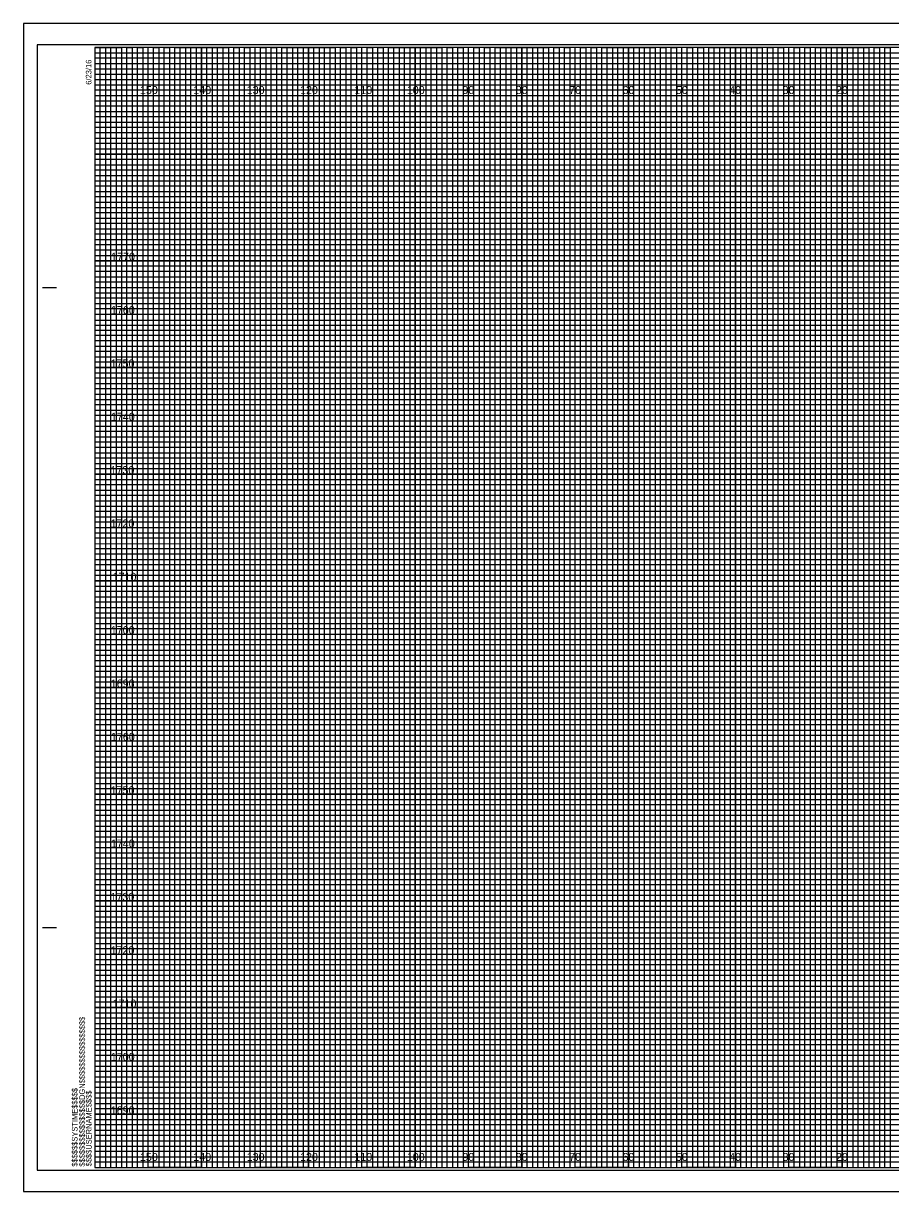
# Model space of a CAD drawing. Extents: x -13 to 1780, y -15 to 3284.
# Drawn here: x 1443.3 to 1605.8, y 865.2 to 1084.2 of the extents above; entities that cross this region are included whole.
import ezdxf

# ---------------------------------------------------------------- set-up
doc = ezdxf.new("R2010")
doc.units = 0
for name, color, linetype in [('Prop Retaining Wall', 7, 'Continuous'), ('Prop SS Cut Line', 7, 'Continuous'), ('Prop SS Fill Line', 7, 'Continuous'), ('Prop SS Transition Line', 7, 'Continuous'), ('Prop XS Earthwork Shape', 7, 'Continuous'), ('Prop XS Noise Wall', 7, 'Continuous'), ('Prop XS Station Labels', 7, 'Continuous'), ('Raster_Level_0', 7, 'Continuous'), ('Scratch_Level_3', 7, 'Continuous'), ('Scratch_Level_7', 7, 'Continuous'), ('Typical Bridge Rail CELL', 7, 'Continuous')]:
    doc.layers.add(name, color=color, linetype=linetype)

msp = doc.modelspace()

# ---------------------------------------------------------------- linework, layer by layer
at = {"layer": 'Prop Retaining Wall'}
for p, q in [((1446.88, 1034.71), (1449.38, 1034.71)), ((1446.98, 1034.71), (1449.48, 1034.71)), ((1446.88, 914.71), (1449.38, 914.71)), ((1446.98, 914.71), (1449.48, 914.71)), ((1456.68, 869.71), (1456.68, 869.71)), ((1456.68, 869.71), (1456.68, 869.71)), ((1456.68, 869.71), (1456.68, 869.71)), ((1456.68, 869.71), (1456.68, 869.71)), ((1456.68, 869.71), (1456.68, 869.71)), ((1456.68, 869.71), (1456.68, 869.71)), ((1456.68, 869.71), (1456.68, 869.71))]:
    msp.add_line(p, q, dxfattribs=at)
msp.add_lwpolyline([(1776.68, 1079.71), (1456.68, 1079.71), (1456.68, 869.71), (1776.68, 869.71)], close=True, dxfattribs=at)
at = {"layer": 'Prop SS Cut Line'}
for points in [[(1456.68, 1079.71), (1461.68, 1079.71), (1461.68, 869.71), (1471.68, 869.71), (1471.68, 1079.71), (1481.68, 1079.71), (1481.68, 869.71), (1491.68, 869.71), (1491.68, 1079.71), (1501.68, 1079.71), (1501.68, 869.71), (1511.68, 869.71), (1511.68, 1079.71), (1521.68, 1079.71), (1521.68, 869.71), (1531.68, 869.71), (1531.68, 1079.71), (1541.68, 1079.71), (1541.68, 869.71), (1551.68, 869.71), (1551.68, 1079.71), (1561.68, 1079.71), (1561.68, 869.71), (1571.68, 869.71), (1571.68, 1079.71), (1581.68, 1079.71), (1581.68, 869.71), (1591.68, 869.71), (1591.68, 1079.71), (1601.68, 1079.71), (1601.68, 869.71), (1611.68, 869.71)], [(1456.68, 1074.71), (1731.68, 1074.71)], [(1456.68, 1054.71), (1776.68, 1054.71), (1776.68, 1064.71), (1456.68, 1064.71)], [(1456.68, 1034.71), (1776.68, 1034.71), (1776.68, 1044.71), (1456.68, 1044.71)], [(1456.68, 1014.71), (1776.68, 1014.71), (1776.68, 1024.71), (1456.68, 1024.71)], [(1456.68, 994.71), (1776.68, 994.71), (1776.68, 1004.71), (1456.68, 1004.71)], [(1456.68, 974.71), (1776.68, 974.71), (1776.68, 984.71), (1456.68, 984.71)], [(1456.68, 954.71), (1776.68, 954.71), (1776.68, 964.71), (1456.68, 964.71)], [(1456.68, 934.71), (1776.68, 934.71), (1776.68, 944.71), (1456.68, 944.71)], [(1456.68, 914.71), (1776.68, 914.71), (1776.68, 924.71), (1456.68, 924.71)], [(1456.68, 894.71), (1776.68, 894.71), (1776.68, 904.71), (1456.68, 904.71)], [(1456.68, 874.71), (1776.68, 874.71), (1776.68, 884.71), (1456.68, 884.71)]]:
    msp.add_lwpolyline(points, dxfattribs=at)
at = {"layer": 'Prop SS Fill Line'}
for p, q in [((1466.68, 1079.71), (1456.68, 1079.71)), ((1466.68, 869.71), (1466.68, 1079.71)), ((1486.68, 1079.71), (1476.68, 1079.71)), ((1476.68, 1079.71), (1476.68, 869.71)), ((1486.68, 869.71), (1486.68, 1079.71)), ((1506.68, 1079.71), (1496.68, 1079.71)), ((1496.68, 1079.71), (1496.68, 869.71)), ((1506.68, 869.71), (1506.68, 1079.71)), ((1526.68, 1079.71), (1516.68, 1079.71)), ((1516.68, 1079.71), (1516.68, 869.71)), ((1526.68, 869.71), (1526.68, 1079.71)), ((1546.68, 1079.71), (1536.68, 1079.71)), ((1536.68, 1079.71), (1536.68, 869.71)), ((1546.68, 869.71), (1546.68, 1079.71)), ((1566.68, 1079.71), (1556.68, 1079.71)), ((1556.68, 1079.71), (1556.68, 869.71)), ((1566.68, 869.71), (1566.68, 1079.71)), ((1586.68, 1079.71), (1576.68, 1079.71)), ((1576.68, 1079.71), (1576.68, 869.71)), ((1586.68, 869.71), (1586.68, 1079.71)), ((1606.68, 1079.71), (1596.68, 1079.71)), ((1596.68, 1079.71), (1596.68, 869.71)), ((1476.68, 869.71), (1466.68, 869.71)), ((1496.68, 869.71), (1486.68, 869.71)), ((1516.68, 869.71), (1506.68, 869.71)), ((1536.68, 869.71), (1526.68, 869.71)), ((1556.68, 869.71), (1546.68, 869.71)), ((1576.68, 869.71), (1566.68, 869.71)), ((1596.68, 869.71), (1586.68, 869.71))]:
    msp.add_line(p, q, dxfattribs=at)
for points in [[(1456.68, 1069.71), (1776.68, 1069.71), (1776.68, 1059.71), (1456.68, 1059.71)], [(1456.68, 1049.71), (1776.68, 1049.71), (1776.68, 1039.71), (1456.68, 1039.71)], [(1456.68, 1029.71), (1776.68, 1029.71), (1776.68, 1019.71), (1456.68, 1019.71)], [(1456.68, 1009.71), (1776.68, 1009.71), (1776.68, 999.71), (1456.68, 999.71)], [(1456.68, 989.71), (1776.68, 989.71), (1776.68, 979.71), (1456.68, 979.71)], [(1456.68, 969.71), (1776.68, 969.71), (1776.68, 959.71), (1456.68, 959.71)], [(1456.68, 949.71), (1776.68, 949.71), (1776.68, 939.71), (1456.68, 939.71)], [(1456.68, 929.71), (1776.68, 929.71), (1776.68, 919.71), (1456.68, 919.71)], [(1456.68, 909.71), (1776.68, 909.71), (1776.68, 899.71), (1456.68, 899.71)], [(1456.68, 889.71), (1776.68, 889.71), (1776.68, 879.71), (1456.68, 879.71)]]:
    msp.add_lwpolyline(points, dxfattribs=at)
at = {"layer": 'Prop SS Transition Line'}
for p, q in [((1456.68, 1078.71), (1716.68, 1078.71)), ((1716.68, 1077.69), (1456.68, 1077.69)), ((1456.68, 1077.69), (1456.68, 1076.71)), ((1456.68, 1076.71), (1716.68, 1076.71)), ((1716.68, 1075.6), (1456.68, 1075.6)), ((1456.68, 1075.6), (1456.68, 1073.71)), ((1456.68, 1073.71), (1776.68, 1073.71))]:
    msp.add_line(p, q, dxfattribs=at)
for points in [[(1456.68, 1072.71), (1726.68, 1072.71), (1776.68, 1072.71), (1776.68, 1071.71), (1456.68, 1071.71)], [(1456.68, 1070.71), (1776.68, 1070.71), (1776.68, 1068.71), (1456.68, 1068.71)], [(1456.68, 1067.71), (1776.68, 1067.71), (1776.68, 1066.71), (1456.68, 1066.69)], [(1456.68, 1065.71), (1776.68, 1065.71), (1776.68, 1063.71), (1456.68, 1063.71)], [(1456.68, 1062.71), (1776.68, 1062.71), (1776.68, 1061.71), (1456.68, 1061.71)], [(1456.68, 1060.71), (1776.68, 1060.71), (1776.68, 1058.71), (1456.68, 1058.71)], [(1456.68, 1057.71), (1776.68, 1057.71), (1776.68, 1056.71), (1456.68, 1056.71)], [(1456.68, 1055.71), (1776.68, 1055.71), (1776.68, 1053.71), (1456.68, 1053.71)], [(1456.68, 1052.71), (1776.68, 1052.71), (1776.68, 1051.71), (1456.68, 1051.71)], [(1456.68, 1050.71), (1776.68, 1050.71), (1776.68, 1048.71), (1456.68, 1048.71)], [(1456.68, 1047.71), (1776.68, 1047.71), (1776.68, 1046.71), (1456.68, 1046.71)], [(1456.68, 1045.71), (1776.68, 1045.71), (1776.68, 1043.66), (1776.68, 1042.71), (1776.68, 1041.71), (1456.68, 1041.71)], [(1456.68, 1043.71), (1776.68, 1043.71), (1776.68, 1042.71), (1456.68, 1042.71)], [(1456.68, 1040.71), (1776.68, 1040.71), (1776.68, 1038.71), (1456.68, 1038.74)], [(1456.68, 1038.74), (1776.68, 1038.71), (1776.68, 1037.71), (1456.68, 1037.71)], [(1456.68, 1036.71), (1776.68, 1036.71), (1776.68, 1035.71), (1456.68, 1035.71)], [(1456.68, 1033.71), (1776.68, 1033.71), (1776.68, 1032.71), (1456.68, 1032.71)], [(1456.68, 1031.71), (1776.68, 1031.71), (1776.68, 1030.71), (1456.68, 1030.71)], [(1456.61, 1028.6), (1776.68, 1028.6), (1776.68, 1027.59), (1456.61, 1027.59)], [(1456.68, 1026.71), (1776.68, 1026.71), (1776.68, 1025.71), (1456.68, 1025.71)], [(1456.68, 1023.71), (1776.68, 1023.71), (1776.68, 1022.71), (1456.68, 1022.71)], [(1456.68, 1021.71), (1776.68, 1021.71), (1776.68, 1020.71), (1456.68, 1020.71)], [(1456.68, 1018.71), (1776.68, 1018.71), (1776.68, 1017.71), (1456.68, 1017.71)], [(1456.68, 1016.71), (1776.68, 1016.71), (1776.68, 1015.71), (1456.68, 1015.71)], [(1456.68, 1013.71), (1776.68, 1013.71), (1776.68, 1012.71), (1456.68, 1012.71)], [(1456.68, 1011.71), (1776.68, 1011.71), (1776.68, 1010.71), (1456.68, 1010.71)], [(1456.68, 1008.71), (1776.68, 1008.71), (1776.67, 1007.69), (1456.68, 1007.71)], [(1456.68, 1006.71), (1776.68, 1006.71), (1776.68, 1005.71), (1456.68, 1005.71)], [(1456.68, 1003.71), (1776.68, 1003.71), (1776.68, 1002.71), (1456.68, 1002.71)], [(1456.68, 1001.71), (1776.68, 1001.71), (1776.68, 1000.71), (1456.68, 1000.71)], [(1456.68, 998.71), (1776.68, 998.71), (1776.68, 997.71), (1456.68, 997.71)], [(1456.68, 996.71), (1776.68, 996.71), (1776.68, 995.71), (1456.68, 995.71)], [(1456.68, 993.71), (1776.68, 993.71), (1776.68, 992.71), (1456.68, 992.71)], [(1456.68, 991.71), (1776.68, 991.71), (1776.68, 990.71), (1456.68, 990.71)], [(1456.68, 988.71), (1776.68, 988.71), (1776.68, 987.71), (1456.68, 987.71)], [(1456.68, 986.7), (1776.75, 986.62), (1776.68, 985.71), (1456.68, 985.71)], [(1456.68, 983.71), (1776.68, 983.71), (1776.68, 982.71), (1456.68, 982.71)], [(1456.68, 981.71), (1776.68, 981.71), (1776.68, 980.71), (1456.68, 980.71)], [(1456.68, 978.71), (1776.68, 978.71), (1776.68, 977.71), (1456.68, 977.71)], [(1456.68, 976.71), (1776.68, 976.71), (1776.68, 975.71), (1456.68, 975.71)], [(1456.68, 973.71), (1776.68, 973.71), (1776.68, 972.71), (1456.68, 972.71)], [(1456.68, 971.71), (1776.68, 971.71), (1776.68, 970.71), (1456.68, 970.71)], [(1456.68, 968.71), (1776.68, 968.71), (1776.68, 967.71), (1456.68, 967.71)], [(1456.68, 966.71), (1776.68, 966.71), (1776.68, 965.71), (1456.68, 965.71)], [(1456.68, 963.71), (1776.68, 963.71), (1776.68, 962.71), (1456.68, 962.71)], [(1456.68, 961.71), (1776.68, 961.71), (1776.68, 960.71), (1456.68, 960.71)], [(1456.68, 958.71), (1776.68, 958.71), (1776.68, 957.71), (1456.68, 957.71)], [(1456.68, 956.71), (1776.68, 956.71), (1776.68, 955.71), (1456.68, 955.71)], [(1456.68, 953.71), (1776.68, 953.71), (1776.68, 952.71), (1456.68, 952.71)], [(1456.68, 951.71), (1776.68, 951.71), (1776.68, 950.71), (1456.68, 950.71)], [(1456.68, 948.71), (1776.68, 948.71), (1776.67, 947.69), (1456.68, 947.71)], [(1456.68, 946.71), (1776.68, 946.71), (1776.68, 945.71), (1456.68, 945.71)], [(1456.68, 943.71), (1776.68, 943.71), (1776.68, 942.71), (1456.68, 942.71)], [(1456.68, 941.71), (1776.68, 941.71), (1776.68, 940.71), (1456.68, 940.71)], [(1456.68, 938.71), (1776.68, 938.71), (1776.68, 937.71), (1456.68, 937.71)], [(1456.68, 936.71), (1776.68, 936.71), (1776.68, 935.71), (1456.68, 935.71)], [(1456.68, 933.71), (1776.68, 933.71), (1776.68, 932.71), (1456.68, 932.71)], [(1456.68, 931.71), (1776.68, 931.71), (1776.68, 930.71), (1456.68, 930.71)], [(1456.68, 928.71), (1776.68, 928.71), (1776.68, 927.71), (1456.68, 927.71)], [(1456.68, 926.7), (1776.75, 926.62), (1776.68, 925.71), (1456.68, 925.71)], [(1456.68, 923.71), (1776.68, 923.71), (1776.68, 922.71), (1456.68, 922.71)], [(1456.68, 921.71), (1776.68, 921.71), (1776.68, 920.71), (1456.68, 920.71)], [(1456.68, 918.71), (1776.68, 918.71), (1776.68, 917.71), (1456.68, 917.71)], [(1456.68, 916.71), (1776.68, 916.71), (1776.68, 915.71), (1456.68, 915.71)], [(1456.68, 913.71), (1776.68, 913.71), (1776.68, 912.71), (1456.68, 912.71)], [(1456.68, 911.71), (1776.68, 911.71), (1776.68, 910.71), (1456.68, 910.71)], [(1456.68, 908.71), (1776.68, 908.71), (1776.68, 907.71), (1456.68, 907.71)], [(1456.68, 906.71), (1776.68, 906.71), (1776.68, 905.71), (1456.68, 905.71)], [(1456.68, 903.71), (1776.68, 903.71), (1776.68, 902.71), (1456.68, 902.71)], [(1456.68, 901.71), (1776.68, 901.71), (1776.68, 900.71), (1456.68, 900.71)], [(1456.68, 898.71), (1776.68, 898.71), (1776.68, 897.71), (1456.68, 897.71)], [(1456.68, 896.71), (1776.68, 896.71), (1776.68, 895.71), (1456.68, 895.71)], [(1456.68, 893.71), (1776.68, 893.71), (1776.68, 892.71), (1456.68, 892.71)], [(1456.68, 891.71), (1776.68, 891.71), (1776.68, 890.71), (1456.68, 890.71)], [(1456.68, 888.71), (1776.68, 888.71), (1776.68, 887.71), (1456.68, 887.71)], [(1456.68, 886.71), (1776.68, 886.71), (1776.68, 885.71), (1456.68, 885.71)], [(1456.68, 883.71), (1776.68, 883.71), (1776.68, 882.71), (1456.68, 882.71)], [(1456.68, 881.71), (1776.68, 881.71), (1776.68, 880.71), (1456.68, 880.71)], [(1456.68, 878.71), (1776.68, 878.71), (1776.68, 877.71), (1456.68, 877.71)], [(1456.68, 876.71), (1776.68, 876.71), (1776.68, 875.71), (1456.68, 875.71)], [(1456.68, 873.71), (1776.68, 873.71), (1776.68, 872.71), (1456.68, 872.71)], [(1456.68, 871.71), (1776.68, 871.71), (1776.68, 870.71), (1456.68, 870.71)]]:
    msp.add_lwpolyline(points, dxfattribs=at)
at = {"layer": 'Prop XS Earthwork Shape'}
msp.add_lwpolyline([(1443.28, 865.21), (1779.98, 865.21), (1779.98, 1084.21), (1443.28, 1084.21)], close=True, dxfattribs=at)
at = {"layer": 'Prop XS Noise Wall'}
for p, q in [((1466.68, 869.71), (1466.68, 1079.71)), ((1476.68, 869.71), (1476.68, 1079.71)), ((1486.68, 869.71), (1486.68, 1079.71)), ((1496.68, 869.71), (1496.68, 1079.71)), ((1506.68, 869.71), (1506.68, 1079.71)), ((1516.68, 869.71), (1516.68, 1079.71)), ((1526.68, 869.71), (1526.68, 1079.71)), ((1536.68, 869.71), (1536.68, 1079.71)), ((1546.68, 869.71), (1546.68, 1079.71)), ((1556.68, 869.71), (1556.68, 1079.71)), ((1566.68, 869.71), (1566.68, 1079.71)), ((1576.68, 869.71), (1576.68, 1079.71)), ((1586.68, 869.71), (1586.68, 1079.71)), ((1596.68, 869.71), (1596.68, 1079.71)), ((1456.68, 1069.71), (1776.68, 1069.71)), ((1456.68, 1059.71), (1776.68, 1059.71)), ((1456.68, 1049.71), (1776.68, 1049.71)), ((1456.68, 1039.71), (1776.68, 1039.71)), ((1456.68, 1029.71), (1776.68, 1029.71)), ((1456.68, 1019.71), (1776.68, 1019.71)), ((1456.68, 1009.71), (1776.68, 1009.71)), ((1456.68, 999.71), (1776.68, 999.71)), ((1456.68, 989.71), (1776.68, 989.71)), ((1456.68, 979.71), (1776.68, 979.71)), ((1456.68, 969.71), (1776.68, 969.71)), ((1456.68, 959.71), (1776.68, 959.71)), ((1456.68, 949.71), (1776.68, 949.71)), ((1456.68, 939.71), (1776.68, 939.71)), ((1456.68, 929.71), (1776.68, 929.71)), ((1456.68, 919.71), (1776.68, 919.71)), ((1456.68, 909.71), (1776.68, 909.71)), ((1456.68, 899.71), (1776.68, 899.71)), ((1456.68, 889.71), (1776.68, 889.71)), ((1456.68, 879.71), (1776.68, 879.71))]:
    msp.add_line(p, q, dxfattribs=at)
at = {"layer": 'Prop XS Station Labels'}
for p, q in [((1779.98, 1084.21), (1443.28, 1084.21)), ((1443.28, 1084.21), (1443.28, 865.21)), ((1443.28, 865.21), (1779.98, 865.21))]:
    msp.add_line(p, q, dxfattribs=at)
at = {"layer": 'Scratch_Level_7'}
msp.add_lwpolyline([(1445.88, 869.21), (1779.08, 869.21), (1779.08, 1080.21), (1445.88, 1080.21)], close=True, dxfattribs=at)
at = {"layer": 'Typical Bridge Rail CELL'}
for points in [[(1456.68, 869.71), (1457.68, 869.71), (1457.68, 1079.71), (1458.68, 1079.71), (1458.68, 869.71)], [(1458.68, 869.71), (1459.68, 869.71), (1459.68, 1079.71), (1460.68, 1079.71), (1460.68, 869.71)], [(1461.68, 869.71), (1462.68, 869.71), (1462.68, 1079.71), (1463.68, 1079.71), (1463.68, 869.71)], [(1463.68, 869.71), (1464.68, 869.71), (1464.68, 1079.71), (1465.68, 1079.71), (1465.68, 869.71)], [(1466.68, 869.71), (1467.68, 869.71), (1467.68, 1079.71), (1468.68, 1079.71), (1468.68, 869.71)], [(1468.68, 869.71), (1469.68, 869.71), (1469.68, 1079.71), (1470.68, 1079.71), (1470.68, 869.71)], [(1471.68, 869.71), (1472.68, 869.71), (1472.68, 1079.71), (1473.68, 1079.71), (1473.68, 869.71)], [(1473.68, 869.71), (1474.68, 869.71), (1474.68, 1079.71), (1475.68, 1079.71), (1475.68, 869.71)], [(1476.68, 869.71), (1477.68, 869.71), (1477.68, 1079.71), (1478.68, 1079.71), (1478.68, 869.71)], [(1478.68, 869.71), (1479.68, 869.71), (1479.68, 1079.71), (1480.68, 1079.71), (1480.68, 869.71)], [(1481.68, 869.71), (1482.68, 869.71), (1482.68, 1079.71), (1483.68, 1079.71), (1483.68, 869.71)], [(1483.68, 869.71), (1484.68, 869.71), (1484.68, 1079.71), (1485.68, 1079.71), (1485.68, 869.71)], [(1486.68, 869.71), (1487.68, 869.71), (1487.68, 1079.71), (1488.68, 1079.71), (1488.68, 869.71)], [(1488.68, 869.71), (1489.68, 869.71), (1489.68, 1079.71), (1490.68, 1079.71), (1490.68, 869.71)], [(1491.68, 869.71), (1492.68, 869.71), (1492.68, 1079.71), (1493.68, 1079.71), (1493.68, 869.71)], [(1493.68, 869.71), (1494.68, 869.71), (1494.68, 1079.71), (1495.68, 1079.71), (1495.68, 869.71)], [(1496.68, 869.71), (1497.68, 869.71), (1497.68, 1079.71), (1498.68, 1079.71), (1498.68, 869.71)], [(1498.68, 869.71), (1499.68, 869.71), (1499.68, 1079.71), (1500.68, 1079.71), (1500.68, 869.71)], [(1501.68, 869.71), (1502.68, 869.71), (1502.68, 1079.71), (1503.68, 1079.71), (1503.68, 869.71)], [(1503.68, 869.71), (1504.68, 869.71), (1504.68, 1079.71), (1505.68, 1079.71), (1505.68, 869.71)], [(1506.68, 869.71), (1507.68, 869.71), (1507.68, 1079.71), (1508.68, 1079.71), (1508.68, 869.71)], [(1508.68, 869.71), (1509.68, 869.71), (1509.68, 1079.71), (1510.68, 1079.71), (1510.68, 869.71)], [(1511.68, 869.71), (1512.68, 869.71), (1512.68, 1079.71), (1513.68, 1079.71), (1513.68, 869.71)], [(1513.68, 869.71), (1514.68, 869.71), (1514.68, 1079.71), (1515.68, 1079.71), (1515.68, 869.71)], [(1516.68, 869.71), (1517.68, 869.71), (1517.68, 1079.71), (1518.68, 1079.71), (1518.68, 869.71)], [(1518.68, 869.71), (1519.68, 869.71), (1519.68, 1079.71), (1520.68, 1079.71), (1520.68, 869.71)], [(1521.68, 869.71), (1522.68, 869.71), (1522.68, 1079.71), (1523.68, 1079.71), (1523.68, 869.71)], [(1523.68, 869.71), (1524.68, 869.71), (1524.68, 1079.71), (1525.68, 1079.71), (1525.68, 869.71)], [(1526.68, 869.71), (1527.68, 869.71), (1527.68, 1079.71), (1528.68, 1079.71), (1528.68, 869.71)], [(1528.68, 869.71), (1529.68, 869.71), (1529.68, 1079.71), (1530.68, 1079.71), (1530.68, 869.71)], [(1531.68, 869.71), (1532.68, 869.71), (1532.68, 1079.71), (1533.68, 1079.71), (1533.68, 869.71)], [(1533.68, 869.71), (1534.68, 869.71), (1534.68, 1079.71), (1535.68, 1079.71), (1535.68, 869.71)], [(1536.68, 869.71), (1537.68, 869.71), (1537.68, 1079.71), (1538.68, 1079.71), (1538.68, 869.71)], [(1538.68, 869.71), (1539.68, 869.71), (1539.68, 1079.71), (1540.68, 1079.71), (1540.68, 869.71)], [(1541.68, 869.71), (1542.68, 869.71), (1542.68, 1079.71), (1543.68, 1079.71), (1543.68, 869.71)], [(1543.68, 869.71), (1544.68, 869.71), (1544.68, 1079.71), (1545.68, 1079.71), (1545.68, 869.71)], [(1546.68, 869.71), (1547.68, 869.71), (1547.68, 1079.71), (1548.68, 1079.71), (1548.68, 869.71)], [(1548.68, 869.71), (1549.68, 869.71), (1549.68, 1079.71), (1550.68, 1079.71), (1550.68, 869.71)], [(1551.68, 869.71), (1552.68, 869.71), (1552.68, 1079.71), (1553.68, 1079.71), (1553.68, 869.71)], [(1553.68, 869.71), (1554.68, 869.71), (1554.68, 1079.71), (1555.68, 1079.71), (1555.68, 869.71)], [(1556.68, 869.71), (1557.68, 869.71), (1557.68, 1079.71), (1558.68, 1079.71), (1558.68, 869.71)], [(1558.68, 869.71), (1559.68, 869.71), (1559.68, 1079.71), (1560.68, 1079.71), (1560.68, 869.71)], [(1561.68, 869.71), (1562.68, 869.71), (1562.68, 1079.71), (1563.68, 1079.71), (1563.68, 869.71)], [(1563.68, 869.71), (1564.68, 869.71), (1564.68, 1079.71), (1565.68, 1079.71), (1565.68, 869.71)], [(1566.68, 869.71), (1567.68, 869.71), (1567.68, 1079.71), (1568.68, 1079.71), (1568.68, 869.71)], [(1568.68, 869.71), (1569.68, 869.71), (1569.68, 1079.71), (1570.68, 1079.71), (1570.68, 869.71)], [(1571.68, 869.71), (1572.68, 869.71), (1572.68, 1079.71), (1573.68, 1079.71), (1573.68, 869.71)], [(1573.68, 869.71), (1574.68, 869.71), (1574.68, 1079.71), (1575.68, 1079.71), (1575.68, 869.71)], [(1576.68, 869.71), (1577.68, 869.71), (1577.68, 1079.71), (1578.68, 1079.71), (1578.68, 869.71)], [(1578.68, 869.71), (1579.68, 869.71), (1579.68, 1079.71), (1580.68, 1079.71), (1580.68, 869.71)], [(1581.68, 869.71), (1582.68, 869.71), (1582.68, 1079.71), (1583.68, 1079.71), (1583.68, 869.71)], [(1583.68, 869.71), (1584.68, 869.71), (1584.68, 1079.71), (1585.68, 1079.71), (1585.68, 869.71)], [(1586.68, 869.71), (1587.68, 869.71), (1587.68, 1079.71), (1588.68, 1079.71), (1588.68, 869.71)], [(1588.68, 869.71), (1589.68, 869.71), (1589.68, 1079.71), (1590.68, 1079.71), (1590.68, 869.71)], [(1591.68, 869.71), (1592.68, 869.71), (1592.68, 1079.71), (1593.68, 1079.71), (1593.68, 869.71)], [(1593.68, 869.71), (1594.68, 869.71), (1594.68, 1079.71), (1595.68, 1079.71), (1595.68, 869.71)], [(1596.68, 869.71), (1597.68, 869.71), (1597.68, 1079.71), (1598.68, 1079.71), (1598.68, 869.71)], [(1598.68, 869.71), (1599.68, 869.71), (1599.68, 1079.71), (1600.68, 1079.71), (1600.68, 869.71)], [(1601.68, 869.71), (1602.68, 869.71), (1602.68, 1079.71), (1603.68, 1079.71), (1603.68, 869.71)], [(1603.68, 869.71), (1604.68, 869.71), (1604.68, 1079.71), (1605.68, 1079.71), (1605.68, 869.71)]]:
    msp.add_lwpolyline(points, dxfattribs=at)

# ---------------------------------------------------------------- texts
at = {"layer": 'Prop Retaining Wall'}
for s, p in [('6/23/16', (1456.03, 1072.71)), ('$$$$$$$$$$$$$$$$DGN$$$$$$$$$$$$$$$$', (1454.8, 869.89)), ('$$$$$$SYSTIME$$$$$', (1453.42, 869.89)), ('$$$$USERNAME$$$$', (1456.06, 869.94))]:
    msp.add_text(s, height=1.05, rotation=90, dxfattribs=at).set_placement(p)
at = {"layer": 'Raster_Level_0'}
for s, p in [('150', (1465.12, 1070.96)), ('140', (1475.12, 1070.96)), ('130', (1485.12, 1070.96)), ('120', (1495.12, 1070.96)), ('110', (1505.3, 1070.96)), ('100', (1515.12, 1070.96)), ('90', (1525.53, 1070.96)), ('80', (1535.53, 1070.96)), ('70', (1545.53, 1070.96)), ('60', (1555.53, 1070.96)), ('50', (1565.53, 1070.96)), ('40', (1575.53, 1070.96)), ('30', (1585.53, 1070.96)), ('20', (1595.53, 1070.96)), ('150', (1465.12, 870.96)), ('140', (1475.12, 870.96)), ('130', (1485.12, 870.96)), ('120', (1495.12, 870.96)), ('110', (1505.3, 870.96)), ('100', (1515.12, 870.96)), ('90', (1525.53, 870.96)), ('80', (1535.53, 870.96)), ('70', (1545.53, 870.96)), ('60', (1555.53, 870.96)), ('50', (1565.53, 870.96)), ('40', (1575.53, 870.96)), ('30', (1585.53, 870.96)), ('20', (1595.53, 870.96))]:
    msp.add_text(s, height=1.5, dxfattribs=at).set_placement(p)
at = {"layer": 'Scratch_Level_3'}
for s, p in [('1770', (1459.72, 1039.71)), ('1760', (1459.68, 1029.71)), ('1750', (1459.63, 1019.71)), ('1740', (1459.68, 1009.71)), ('1730', (1459.6, 999.71)), ('1720', (1459.61, 989.71)), ('1710', (1459.99, 979.71)), ('1700', (1459.66, 969.71)), ('1690', (1459.65, 959.71)), ('1760', (1459.68, 949.71)), ('1750', (1459.63, 939.71)), ('1740', (1459.68, 929.71)), ('1730', (1459.6, 919.71)), ('1720', (1459.61, 909.71)), ('1710', (1459.99, 899.71)), ('1700', (1459.66, 889.71)), ('1690', (1459.65, 879.71))]:
    msp.add_text(s, height=1.5, dxfattribs=at).set_placement(p)

doc.saveas('drawing.dxf')
